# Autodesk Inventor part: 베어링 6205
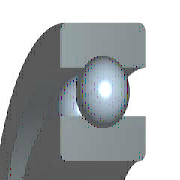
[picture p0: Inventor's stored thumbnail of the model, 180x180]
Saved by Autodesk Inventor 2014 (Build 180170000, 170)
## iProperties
Company: 한국ATC센터
IsCustomPart: 1
Created: 2009-02
Part Number: 베어링 6205
Material: Steel, Mild
Description: 깊은 그루브 볼 베어링
Document SubType Name: Modeling
Standard: KS B 2023
Designer: KYOUNG IL JANG
Standards Organization: KS
Language: ko-KR
Size Designation: 6205 - 25 x 52 x 15
Categories: <MemberInstance><Categories><Category DisplayName="샤프트 부품" InternalName="7f7aeb1f-a693-4053-b835-cee3144e0d98" Mnemonic="SHFT"><Category DisplayName="베어링" Inter
Density: 1 g/cm^3
Appearance: Steel
Author: KYOUNG IL JANG
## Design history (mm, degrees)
revolve "본체" stored, may be unused: angle "d6" = 90 deg
revolve "볼" stored, may be unused: angle "d7" = 90 deg
pattern_circular "IDS_ARRAYBALL[SIMPL:T]" dims angle "d3" = 360 deg
body "Solid1"
sketch "스케치" dims "d0" = 7.02 (= -0.26 x WD + 0.26 x BD)
  geometry: L1 (3.99, 19.25)-(11.01, 19.25); L2 (7.5, 19.25)-(7.5, 15.74); L3 (7.5, 19.25)-(7.5, 22.76); L4 (4.892, 16.901)-(0, 16.901); L5 (0, 12.5)-(15, 12.5); L6 (4.892, 21.599)-(0, 21.599); L7 (0, 26)-(15, 26); L8 (15, 12.5)-(15, 16.901); L9 (10.108, 16.901)-(15, 16.901); L10 (10.108, 21.599)-(15, 21.599); L11 (15, 26)-(15, 21.599); L12 (-1.4, 0)-(8.4, 0) reference; L13 (0, -0.3)-(0, 5.3) reference
  constraints: 22 end point, 4 point on line, 2 collinear, 2 perpendicular, 2 symmetric about line, 1 midpoint, 1 parallel, 14 other
  dimensions: "d9" = 25 diameter of L5 L12 (= WD); "d11" = 52 diameter of L7 L12 (= BD); "d12" = 15 distance between parallel lines of L8 L13 (= KB); "d13" = 33.802 diameter of L9 L12 (= 0.326 x BD + 0.674 x WD)
fillet "모깎기1" dims "d1" = 1 (= KRS)
other parameters: "WD" = 25 [user parameter; used in 5 equation terms], "BD" = 52 [user parameter; used in 5 equation terms], "KB" = 15 [user parameter; used in 1 equation term], "KRS" = 1 [user parameter; used in 1 equation term], "d4" = 0, "d5" = 0, "d8" = 0, "d14" = 0, "d15" = 0, "BBA" = 0 [user parameter], "BC0" = 7800000 [user parameter], "BC" = 1.4e+07 [user parameter], "BR" = 26 (= 0.5 x BD) [user parameter], "WR" = 12.5 (= 0.5 x WD) [user parameter]
